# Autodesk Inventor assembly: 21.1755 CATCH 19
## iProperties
Created: 2007-03
Part Number: 21.1755 CATCH 19
Document SubType Name: Assembly
Designer: Andy Moles
Mass: 144.128 g
Surface Area: 252.556 cm^2
Volume: 46.4016 cm^3
Density: 3.1061 g/cm^3
Author: Andy Moles
